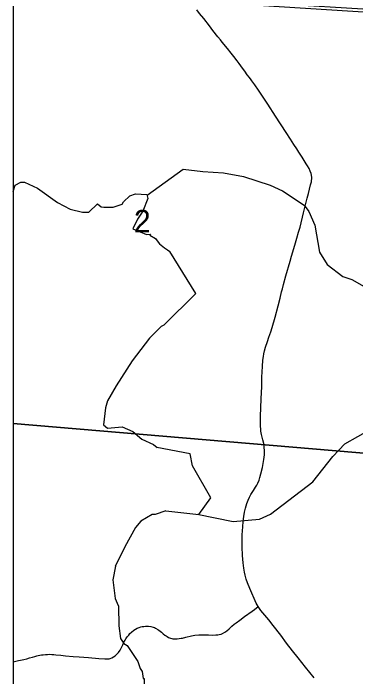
# Model space of a CAD drawing. Extents: x 396.2 to 468.4, y 232.6 to 279.1.
# Drawn here: x 413.851 to 414.49, y 275.483 to 276.722 of the extents above; entities that cross this region are included whole.
import ezdxf

# ---------------------------------------------------------------- set-up
doc = ezdxf.new("R2010")
doc.units = 0
for name, color, linetype in [('Default', 7, 'Continuous'), ('GM_X_County_Road', 7, 'Continuous'), ('GM_X_Minor_River', 7, 'Continuous'), ('GM_X_Section_Text', 7, 'Continuous'), ('SH_Cut_Line', 7, 'Continuous'), ('TX_P_1', 7, 'Continuous')]:
    doc.layers.add(name, color=color, linetype=linetype)

msp = doc.modelspace()

# ---------------------------------------------------------------- linework, layer by layer
at = {"layer": 'Default'}
for points in [[(413.8513, 276.7696), (413.8513, 275.9557), (414.5706, 275.8945), (414.6352, 276.7213), (414.6257, 276.7217)], [(413.8513, 275.9557), (413.8513, 274.9056), (414.5003, 274.8549), (414.5706, 275.8945)]]:
    msp.add_lwpolyline(points, close=True, dxfattribs=at)
msp.add_lwpolyline([(415.3087, 271.617), (415.3585, 272.2209), (415.4595, 273.6806), (415.4838, 274.0061), (415.5736, 275.3305), (415.6062, 275.8993), (415.6444, 276.6015), (415.6445, 276.6023), (415.6478, 276.651), (415.1704, 276.681), (414.1803, 276.7441), (413.8513, 276.7667), (413.8513, 270.6726)], dxfattribs=at)
at = {"layer": 'GM_X_County_Road'}
for points in [[(414.4121, 275.4809), (414.3961, 275.5007), (414.3824, 275.5184), (414.372, 275.5315), (414.361, 275.5458), (414.3499, 275.5607), (414.3362, 275.5784), (414.3276, 275.589), (414.3241, 275.5934), (414.313, 275.6068), (414.3089, 275.6121), (414.3077, 275.614), (414.3058, 275.6174), (414.3041, 275.6205), (414.2923, 275.6479), (414.2881, 275.6582), (414.2856, 275.6652), (414.2836, 275.6723), (414.2822, 275.6783), (414.281, 275.6855), (414.2798, 275.6959), (414.2789, 275.7094), (414.2783, 275.7254), (414.2782, 275.7353), (414.2784, 275.7477), (414.2791, 275.7626), (414.2799, 275.7731), (414.2804, 275.7778), (414.2811, 275.7823), (414.2825, 275.7901), (414.2844, 275.7979), (414.2869, 275.8062), (414.2892, 275.8125), (414.2917, 275.8181), (414.2942, 275.823), (414.299, 275.8309), (414.3031, 275.837), (414.3053, 275.8408), (414.307, 275.8441), (414.3095, 275.8499), (414.3113, 275.8552), (414.3132, 275.8618), (414.3159, 275.8739), (414.3186, 275.8886), (414.3197, 275.8973), (414.3199, 275.9011), (414.3198, 275.9048), (414.3193, 275.9117), (414.3182, 275.9185), (414.3168, 275.9252), (414.3143, 275.9354), (414.3131, 275.9414), (414.3126, 275.9457), (414.3123, 275.9499), (414.3121, 275.9585), (414.3124, 275.969), (414.3137, 276.0015), (414.3146, 276.0248), (414.3149, 276.0354), (414.315, 276.0422), (414.316, 276.062), (414.3168, 276.0737), (414.3178, 276.0811), (414.3187, 276.0859), (414.3198, 276.0913), (414.3218, 276.0985), (414.3251, 276.1085), (414.3279, 276.1167), (414.3314, 276.1266), (414.3341, 276.1349), (414.3398, 276.154), (414.3454, 276.1751), (414.3488, 276.1896), (414.3516, 276.2017), (414.353, 276.2071), (414.3552, 276.2155), (414.3596, 276.2315), (414.3675, 276.2589), (414.3701, 276.2678), (414.3764, 276.2884), (414.3803, 276.3015), (414.3834, 276.3128), (414.386, 276.3224), (414.3926, 276.349), (414.3994, 276.3761), (414.4015, 276.3851), (414.4058, 276.4014), (414.4071, 276.4069), (414.4075, 276.4095), (414.4078, 276.4126), (414.4077, 276.4151), (414.4072, 276.4195), (414.4065, 276.4227), (414.4051, 276.4269), (414.4028, 276.432), (414.4001, 276.4366), (414.3977, 276.4407), (414.3898, 276.4526), (414.3837, 276.462), (414.3798, 276.4683), (414.3744, 276.4766), (414.368, 276.4866), (414.3599, 276.4991), (414.3404, 276.5294), (414.3259, 276.5516), (414.3136, 276.5703), (414.3085, 276.578), (414.3017, 276.5877), (414.2963, 276.5953), (414.2949, 276.5973), (414.2915, 276.6018), (414.2877, 276.6067), (414.2829, 276.6132), (414.2785, 276.6191), (414.2724, 276.6277), (414.2687, 276.6328), (414.2627, 276.6406), (414.2577, 276.647), (414.2507, 276.6557), (414.2409, 276.6677), (414.2375, 276.672), (414.2328, 276.6778), (414.2237, 276.6896), (414.2172, 276.6979), (414.2065, 276.7115), (414.1987, 276.7213), (414.1933, 276.728)], [(413.8513, 275.511), (413.8562, 275.5121), (413.861, 275.5131), (413.8648, 275.5139), (413.8708, 275.5153), (413.8766, 275.5167), (413.8815, 275.518), (413.8872, 275.5196), (413.8912, 275.5207), (413.8951, 275.5218), (413.898, 275.5225), (413.9009, 275.5231), (413.9039, 275.5236), (413.9073, 275.524), (413.9111, 275.5244), (413.9151, 275.5247), (413.9191, 275.5249), (413.9233, 275.5247), (413.9271, 275.5244), (413.9309, 275.524), (413.9397, 275.5232), (413.9489, 275.5223), (413.9631, 275.521), (413.9742, 275.5201), (413.9829, 275.5194), (413.9916, 275.5187), (414.0107, 275.5172), (414.0218, 275.5163), (414.0274, 275.5162), (414.0299, 275.5164), (414.0317, 275.5169), (414.0352, 275.5181), (414.0384, 275.5199), (414.0414, 275.5221), (414.0446, 275.525), (414.0475, 275.5283), (414.0504, 275.5328), (414.0524, 275.5365), (414.0542, 275.5401), (414.0553, 275.5426), (414.0576, 275.5475), (414.0597, 275.5513), (414.0614, 275.5539), (414.0639, 275.5574), (414.0665, 275.5608), (414.0689, 275.5637), (414.0716, 275.5664), (414.076, 275.5702), (414.0791, 275.572), (414.0823, 275.5737), (414.0858, 275.5751), (414.0894, 275.5761), (414.0918, 275.5766), (414.0945, 275.577), (414.0979, 275.5774), (414.101, 275.5775), (414.1036, 275.5773), (414.1079, 275.5767), (414.1121, 275.5757), (414.1145, 275.5748), (414.1167, 275.5738), (414.121, 275.5713), (414.123, 275.5698), (414.1278, 275.5659), (414.1311, 275.5632), (414.134, 275.5607), (414.1361, 275.5594), (414.1382, 275.558), (414.1409, 275.5565), (414.1443, 275.555), (414.1468, 275.5544), (414.1491, 275.554), (414.1516, 275.5538), (414.1566, 275.5538), (414.1609, 275.5543), (414.1644, 275.5549), (414.167, 275.5553), (414.173, 275.5567), (414.1834, 275.5591), (414.19, 275.5603), (414.1974, 275.5611), (414.2017, 275.5613), (414.2092, 275.5613), (414.2153, 275.5611), (414.2222, 275.5608), (414.229, 275.561), (414.2329, 275.5611), (414.2351, 275.5616), (414.2387, 275.5626), (414.2415, 275.5637), (414.2458, 275.5661), (414.2493, 275.5687), (414.254, 275.5727), (414.2591, 275.5773), (414.2633, 275.5809), (414.2667, 275.5836), (414.2736, 275.5889), (414.2827, 275.5953), (414.2968, 275.6054), (414.3011, 275.6088), (414.3077, 275.614)]]:
    msp.add_lwpolyline(points, dxfattribs=at)
at = {"layer": 'GM_X_Minor_River'}
for points in [[(414.101, 276.3818), (414.1681, 276.4305), (414.2048, 276.4259), (414.2431, 276.4237), (414.2803, 276.4165), (414.3303, 276.4006), (414.353, 276.3903), (414.3936, 276.363), (414.4023, 276.3516), (414.4133, 276.3261), (414.422, 276.2756), (414.4364, 276.2524), (414.4656, 276.2304), (414.4826, 276.2247), (414.5099, 276.2088), (414.516, 276.2053), (414.5633, 276.1932), (414.5831, 276.1803), (414.6092, 276.1655), (414.6316, 276.1583), (414.6524, 276.1656), (414.7351, 276.1934), (414.7718, 276.2079)], [(413.8513, 276.3886), (413.8549, 276.4005), (413.8652, 276.4062), (413.872, 276.4062), (413.8963, 276.3949), (413.9339, 276.368), (413.9574, 276.356), (413.9802, 276.3503), (413.9923, 276.35), (414.0082, 276.3659), (414.015, 276.3602), (414.0203, 276.3595), (414.0374, 276.3595), (414.0541, 276.3649), (414.0571, 276.3698), (414.0684, 276.3808), (414.0794, 276.3846), (414.1006, 276.3835), (414.1022, 276.3759), (414.0928, 276.352), (414.0829, 276.3372), (414.0743, 276.319), (414.0876, 276.3134), (414.0997, 276.3085), (414.1073, 276.3093), (414.1062, 276.3074), (414.1168, 276.3013), (414.1214, 276.2941), (414.124, 276.2911), (414.1335, 276.2839), (414.1388, 276.2801), (414.1435, 276.277)], [(414.1321, 276.1392), (414.1916, 276.1985), (414.1435, 276.277)], [(414.1321, 276.1392), (414.1271, 276.1369), (414.1052, 276.1153), (414.0731, 276.0728), (414.0432, 276.0262), (414.027, 275.9981), (414.0233, 275.9852), (414.0196, 275.953), (414.0268, 275.947), (414.0544, 275.9497), (414.0742, 275.941), (414.0909, 275.9263), (414.1125, 275.9168), (414.1194, 275.9108)], [(414.1943, 275.7863), (414.2611, 275.7728), (414.3104, 275.777), (414.3308, 275.7862), (414.4101, 275.8471), (414.4469, 275.8943), (414.4696, 275.9175), (414.5178, 275.9453)], [(414.1359, 275.7929), (414.1971, 275.7859), (414.2194, 275.8169), (414.1852, 275.8769), (414.1812, 275.8993), (414.1191, 275.911)], [(414.136, 275.7929), (414.1156, 275.7861), (414.1102, 275.7861), (414.0894, 275.7736), (414.0792, 275.7614), (414.0592, 275.7258), (414.0415, 275.689)], [(414.0417, 275.6894), (414.0368, 275.6636), (414.0411, 275.6293), (414.0449, 275.6201), (414.0477, 275.615), (414.0481, 275.5782), (414.0513, 275.5546), (414.0577, 275.5448), (414.0637, 275.5415), (414.0833, 275.5115), (414.0877, 275.4985), (414.0916, 275.493), (414.0934, 275.4796), (414.0956, 275.4799), (414.0953, 275.4625), (414.0948, 275.4599), (414.1005, 275.4319), (414.101, 275.3879), (414.0991, 275.3876), (414.1034, 275.3727), (414.1185, 275.3611), (414.1227, 275.3537), (414.1317, 275.3495), (414.1371, 275.3465)]]:
    msp.add_lwpolyline(points, dxfattribs=at)
at = {"layer": 'SH_Cut_Line'}
msp.add_lwpolyline([(422.4135, 277.8582), (413.8513, 277.8582), (413.8513, 270.6726)], dxfattribs=at)
at = {"layer": 'TX_P_1'}
msp.add_line((413.8513, 277.8582), (413.8513, 264.2582), dxfattribs=at)

# ---------------------------------------------------------------- texts
at = {"layer": 'GM_X_Section_Text'}
msp.add_text('2', height=0.0419, rotation=0, dxfattribs=at).set_placement((414.0763, 276.3126))

doc.saveas('drawing.dxf')
